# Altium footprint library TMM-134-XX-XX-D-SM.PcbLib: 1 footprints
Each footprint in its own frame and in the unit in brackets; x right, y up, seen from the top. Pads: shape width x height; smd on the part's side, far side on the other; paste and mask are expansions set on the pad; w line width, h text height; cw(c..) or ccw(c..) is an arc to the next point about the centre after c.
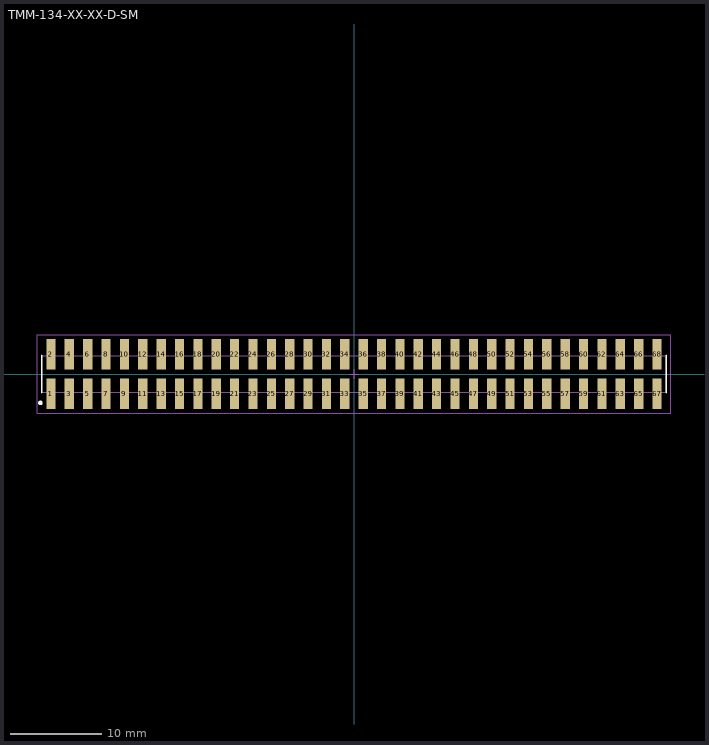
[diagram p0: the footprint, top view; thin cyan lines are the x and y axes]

## TMM-134-XX-XX-D-SM [mm] "2.00mm pitch, 68 pin, terminal strip; double row, SMT"
height 2.77
pads (68):
  rect 1x3.3 smd mask+0: 1(-33,-2.15) 2(-33,2.15) 3(-31,-2.15) 4(-31,2.15) 5(-29,-2.15) 6(-29,2.15) 7(-27,-2.15) 8(-27,2.15) 9(-25,-2.15) 10(-25,2.15) 11(-23,-2.15) 12(-23,2.15) 13(-21,-2.15) 14(-21,2.15) 15(-19,-2.15) 16(-19,2.15) 17(-17,-2.15) 18(-17,2.15) 19(-15,-2.15) 20(-15,2.15) 21(-13,-2.15) 22(-13,2.15) 23(-11,-2.15) 24(-11,2.15) 25(-9,-2.15) 26(-9,2.15) 27(-7,-2.15) 28(-7,2.15) 29(-5,-2.15) 30(-5,2.15) 31(-3,-2.15) 32(-3,2.15) 33(-1,-2.15) 34(-1,2.15) 35(1,-2.15) 36(1,2.15) 37(3,-2.15) 38(3,2.15) 39(5,-2.15) 40(5,2.15) 41(7,-2.15) 42(7,2.15) 43(9,-2.15) 44(9,2.15) 45(11,-2.15) 46(11,2.15) 47(13,-2.15) 48(13,2.15) 49(15,-2.15) 50(15,2.15) 51(17,-2.15) 52(17,2.15) 53(19,-2.15) 54(19,2.15) 55(21,-2.15) 56(21,2.15) 57(23,-2.15) 58(23,2.15) 59(25,-2.15) 60(25,2.15) 61(27,-2.15) 62(27,2.15) 63(29,-2.15) 64(29,2.15) 65(31,-2.15) 66(31,2.15) 67(33,-2.15) 68(33,2.15)
Top Overlay:
  circle w0.25: c-34.15,-3.15 r0.125
  lines w0.2: -34,-2 -34,2 ; 34,-2 34,2
Mechanical 12:
  lines w0.001: -34,-2 -34,2 34,2 34,-2 -34,-2
Mechanical 13:
  lines w0.1: -34,-2 -34,2 34,2 34,-2 -34,-2
  text ".Designator" at 0.127,-0.127 h1.52
Mechanical 15:
  lines w0.05: -0.5,0 0.5,0 ; 0,-0.5 0,0.5 ; -34.5,-4.3 -34.5,4.3 34.5,4.3 34.5,-4.3 -34.5,-4.3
